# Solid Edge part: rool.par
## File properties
Author: Georg
Template: Iso Part.par
Last saved by: Kalle
Revision: 3
Application: Solid Edge
Accuracy: 0,990
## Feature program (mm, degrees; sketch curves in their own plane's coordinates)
sketch for "unnamed Protrusion 1" plane through (0, 0, 0) normal (1, 0, 0) x-axis (0, 1, 0)
  circle centre (0, 0) radius 7.5
extrude "unnamed Protrusion 1" add finite 3 along -normal
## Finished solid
Body 1: solid body, 3 faces, 2 edges, 0 vertices.
  Faces by surface: plane 2, cylinder 1
  Edges by curve: circle 2
Bounding box of the edges (mm): 3.000 x 15.000 x 15.000, from (-3, -7.5, -7.5) to (0, 7.5, 7.5).
Cylindrical faces by radius (mm): R7.5 x1
Planar faces by outward normal: +x 1, -x 1
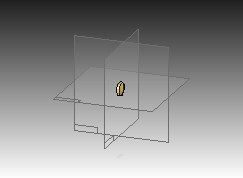
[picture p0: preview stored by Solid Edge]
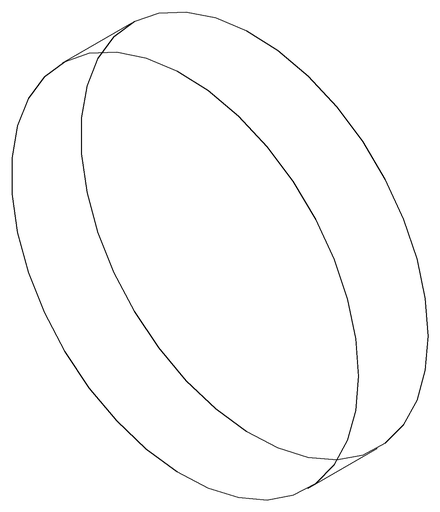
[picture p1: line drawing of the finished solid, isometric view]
